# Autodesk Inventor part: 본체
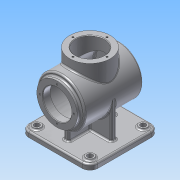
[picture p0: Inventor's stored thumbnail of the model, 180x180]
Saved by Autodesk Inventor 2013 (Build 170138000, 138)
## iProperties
Created: 2015-07
Part Number: 본체
Material: 알루미늄 6061
Document SubType Name: Modeling
Designer: ST5
Density: 2.71 g/cm^3
Mass: 1277.62 g
Surface Area: 1267.64 cm^2
Volume: 471.447 cm^3
Author: ST5
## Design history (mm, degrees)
sketch "스케치1"
  geometry: L1 (-65, 65)-(65, 65); L2 (65, 65)-(65, -65); L3 (65, -65)-(-65, -65); L4 (-65, -65)-(-65, 65); 1 further point
  constraints: 8 end point, 2 parallel, 1 horizontal, 1 perpendicular
  dimensions: "d0" = 130 distance of L1.start L1.end; "d2" = 130 distance of L3.end L1.start; "d3" = 65 distance from line of point (0, 0) L1; "d4" = 65 distance from line of point (0, 0) L4
extrude "돌출1" new body sketch "스케치1" distance "d5" = 10; taper "d6" = 0 deg
node "작업 평면1"
sketch "스케치2"
  geometry: L1 (0, 0)-(0, 78); C1 r 45 at (0, 78)
  constraints: 2 end point, 1 centre point, 1 coincident, 1 vertical
  dimensions: "d8" = 78 distance of L1.start L1.end; "d9" = 90 diameter of C1
extrude "돌출2" join sketch "스케치2" stored distance "d10" = 110; taper "d11" = 0 deg
node "작업 평면2"
sketch "스케치3"
  geometry: L1 (-5, 45)-(5, 45); L2 (5, 45)-(5, -45); L3 (5, -45)-(-5, -45); L4 (-5, -45)-(-5, 45); L5 (-45, 5)-(45, 5); L6 (45, 5)-(45, -5); L7 (45, -5)-(-45, -5); L8 (-45, -5)-(-45, 5); 1 further point
  constraints: 16 end point, 4 parallel, 2 horizontal, 2 perpendicular
  dimensions: "d13" = 10 distance of L1.start L1.end; "d15" = 10 distance of L5.end L6.end; "d16" = 5 distance from line of L5 point (0, 0); "d17" = 5 distance from line of L2 point (0, 0); "d18" = 90 distance of L1.end L2.end; "d19" = 45 distance from line of point (0, 0) L3; "d20" = 90 distance of L5.start L5.end; "d21" = 45 distance from line of point (0, 0) L8
extrude "돌출3" join sketch "스케치3" distance "d22" = 68; taper "d23" = 0 deg
sketch "스케치4"
  geometry: C1 r 45 at (0, 0) reference; C2 r 38 at (0, 0); 1 further point
  constraints: 1 centre point, 1 coincident
  dimensions: "d24" = 76 diameter of C2
extrude "돌출4" join sketch "스케치4" distance "d26" = 7; taper "d27" = 0 deg
fillet "모깎기1" dims "d28" = 15
fillet "모깎기2" dims "d29" = 3
sketch "스케치5"
  geometry: C1 r 7.5 at (50, 50); C2 r 7.5 at (50, -50); C3 r 7.5 at (-50, 50); C4 r 7.5 at (-50, -50); A1 r 12 centre (50, -50) between (50, -62) and (62, -50) reference; A2 r 12 centre (50, 50) between (62, 50) and (50, 62) reference; A3 r 12 centre (-50, 50) between (-50, 62) and (-62, 50) reference; A4 r 12 centre (-50, -50) between (-62, -50) and (-50, -62) reference; 1 further point
  constraints: 4 centre point, 4 coincident
  dimensions: "d31" = 15 diameter of C1; "d33" = 15 diameter of C3; "d34" = 15 diameter of C4; "d35" = 15 diameter of C2
extrude "돌출5" join sketch "스케치5" distance "d36" = 3; taper "d37" = 0 deg
fillet "모깎기3" dims "d38" = 3
sketch "스케치6"
  geometry: C1 r 7.5 at (0, 0) reference; C2 r 5 at (0, 0); 1 further point
  constraints: 1 centre point, 1 coincident
  dimensions: "d39" = 10 diameter of C2
extrude "돌출6" cut sketch "스케치6" distance "d41" = 13; taper "d42" = 0 deg
sketch "스케치7"
  geometry: C1 r 7.5 at (0, 0) reference; C2 r 5 at (0, 0); 1 further point
  constraints: 1 centre point, 1 coincident
  dimensions: "d43" = 10 diameter of C2
extrude "돌출7" cut sketch "스케치7" distance "d45" = 13; taper "d46" = 0 deg
node "작업 평면4"
fillet "모깎기4" dims "d48" = 3
fillet "모깎기5" dims "d49" = 3
fillet "모깎기6" dims "d50" = 3
fillet "모깎기7" dims "d51" = 3
fillet "모깎기8" dims "d52" = 3
fillet "모깎기9" dims "d53" = 3
sketch "스케치8"
  geometry: C1 r 38 at (0, 0) reference; C2 r 27 at (0, 0); 1 further point
  constraints: 1 centre point, 1 coincident
  dimensions: "d54" = 54 diameter of C2
extrude "돌출8" cut sketch "스케치8" distance "d56" = 14; taper "d57" = 0 deg
node "작업 평면6"
sketch "스케치12"
  geometry: C1 r 40 at (0, 78); 1 further point
  constraints: 1 centre point
  dimensions: "d64" = 80 diameter of C1; "d66" = 0 horizontal distance of point (0, 0) C1.centre; "d67" = 78 distance of point (0, 0) C1.centre
extrude "돌출10" cut sketch "스케치12" stored distance "d68" = 96; taper "d69" = 0 deg
fillet "모깎기10" dims "d70" = 3
node "작업 평면7"
sketch "스케치13"
  geometry: 1 further point
node "작업 평면8"
sketch "스케치14"
  geometry: C1 r 38 at (0, 0); 1 further point
  constraints: 1 centre point, 1 coincident
  dimensions: "d78" = 76 diameter of C1
extrude "돌출11" join sketch "스케치14" stored distance "d80" = 96; taper "d81" = 0 deg
fillet "모깎기11" dims "d82" = 3
sketch "스케치15"
  geometry: C1 r 38 at (0, 0) reference; C2 r 27 at (0, 0)
  constraints: 1 centre point, 1 coincident
  dimensions: "d83" = 54 diameter of C2
extrude "돌출12" cut sketch "스케치15" distance "d85" = 50; taper "d86" = 0 deg
chamfer "모따기1" distance "d87" = 1; stored, may be unused: second distance "d88" = 2, angle "d89" = 45 deg
chamfer "모따기2" distance "d90" = 1; stored, may be unused: second distance "d91" = 2, angle "d92" = 45 deg
sketch "스케치16" dims "d95" = 64
  geometry: L1 (0, 0)-(0, 71.782); C1 r 28 at (0, 0) reference; 1 further point
  constraints: 2 end point, 1 coincident, 1 point on line, 1 vertical, 1 vertical alignment, 2 other
hole "구멍1" sketch "스케치16" at (0, 32) diameter "d97" = 3.242; stored, may be unused: countersink angle "d101" = 90 deg, drill point angle "d103" = 118 deg; dims "d98" = 8, "d99" = 4, "d100" = 2, "d102" = 10
sketch "스케치17" dims "d107" = 64
  geometry: L1 (0, 0)-(0, 73.386); C1 r 28 at (0, 0) reference; 2 further points
  constraints: 2 end point, 1 coincident, 1 point on line, 1 vertical, 1 vertical alignment, 2 other
hole "구멍2" sketch "스케치17" at (0, 32) diameter "d109" = 3.242; stored, may be unused: countersink angle "d113" = 90 deg, drill point angle "d115" = 118 deg; dims "d110" = 8, "d111" = 4, "d112" = 2, "d114" = 10
sketch "스케치18"
  geometry: L1 (1.889, 3.602)-(-1.889, 3.602); L2 (-1.889, 3.602)-(-1.889, -3.602); L3 (-1.889, -3.602)-(1.889, -3.602); L4 (1.889, -3.602)-(1.889, 3.602); L5 (-1.889, 0)-(1.889, 0); L6 (0, -3.602)-(0, 3.602); C1 r 42 at (0, 0) reference; 1 further point
  constraints: 4 end point, 2 other
  dimensions: "d119" = 0 distance from line of C1.centre L5; "d120" = 0 distance from line of L6 C1.centre
feature "엠보싱1" sketch "스케치18" dims "d15" = 10, "d16" = 5, "d20" = 90, "d21" = 45, "d121" = 0.5, "d122" = 0
node "솔리드1"
mirror "대칭1"
pattern_circular "원형 패턴1" dims angle "d105" = 360 deg
pattern_circular "원형 패턴2" dims angle "d117" = 360 deg
other parameters: "d7" = 0, "d47" = 0, "d63" = 0, "d71" = 0
